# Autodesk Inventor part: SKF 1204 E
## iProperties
Company: Engineering Services Northland (1988) Ltd
Author: Malcolm
Shininess: 60.0
Length Units: 11269
Angle Units: 11283
Time Units: 11279
Mass Units: 11290
Length Display Precision: 3
Angle Display Precision: 2
Compacted: True
PropertySet Name: _Private Model Information
Created: 2001-11
Part Number: SKF 1204 E
Material: Stainless Steel, Austenitic
Description: Self Aligning Ball
Document SubType Name: Modeling
Designer: Malcolm
Control State: 0
Master: False
Checked Out: False
PropertySet Name: Design Tracking Control
Density: 0.0
Volumn: 0.0
Area: 0.0
PropertySet Name: Model Information
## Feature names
1. Revolution1
2. TaperBore [Revolution]
3. Revolution7
4. Circular Pattern1
5. Revolution3
6. Circular Pattern2
7. Fillet1
8. StraightFillet [Fillet]
9. Seals [Revolution]
10. TaperFillet [Fillet]
